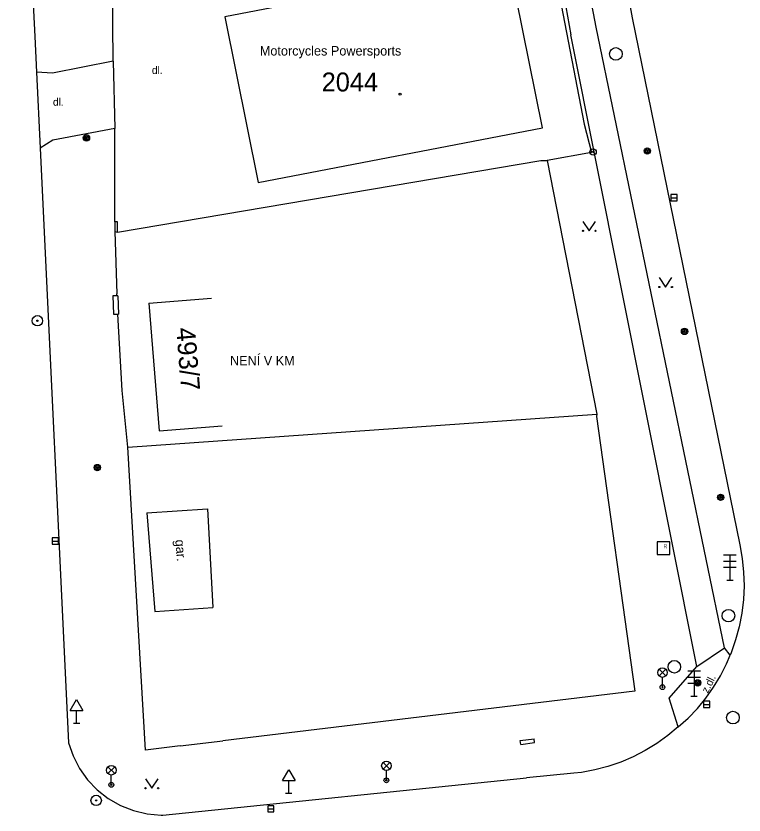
# Model space of a CAD drawing. Extents: x -640201 to -639641, y -1044739 to -1044317.
# Drawn here: x -640163.5 to -640105.9, y -1044617.1 to -1044553.9 of the extents above; entities that cross this region are included whole.
import ezdxf

# ---------------------------------------------------------------- set-up
doc = ezdxf.new("R2010")
doc.units = 0
for name, color, linetype in [('Budovy', 7, 'Continuous'), ('Ploty', 7, 'Continuous'), ('Pol_bod_pole', 7, 'Continuous'), ('Popis objektů', 7, 'Continuous'), ('Popis povrchů', 7, 'Continuous'), ('Popis ČP_ ČE', 7, 'Continuous'), ('Popis-obec_pozn_', 7, 'Continuous'), ('Pris-HUP', 7, 'Continuous'), ('Rozhraní ploch 1', 7, 'Continuous'), ('Rozhraní ploch 2', 7, 'Continuous'), ('Sloupy_označník', 7, 'Continuous'), ('Vstup na pozemky', 7, 'Continuous'), ('Znaky doprava', 7, 'Continuous'), ('Znaky kanalizace', 7, 'Continuous'), ('Značky doprava', 7, 'Continuous'), ('Značky KM', 7, 'Continuous'), ('Značky předmětů', 7, 'Continuous'), ('Šachta sdělovací', 7, 'Continuous')]:
    doc.layers.add(name, color=color, linetype=linetype)

msp = doc.modelspace()

# ---------------------------------------------------------------- linework, layer by layer
at = {"layer": 'Budovy'}
for p, q in [((-640124.51, -1044549.62), (-640147.01, -1044553.94)), ((-640121.86, -1044562.74), (-640124.51, -1044549.62)), ((-640147.01, -1044553.94), (-640144.36, -1044567.06)), ((-640144.36, -1044567.06), (-640121.86, -1044562.74)), ((-640153.03, -1044576.62), (-640148.047, -1044576.21)), ((-640153.03, -1044576.62), (-640152.2, -1044586.72)), ((-640152.2, -1044586.72), (-640147.217, -1044586.31)), ((-640153.18, -1044593.21), (-640148.364, -1044592.877)), ((-640153.18, -1044593.21), (-640152.54, -1044601.02)), ((-640148.364, -1044592.877), (-640147.96, -1044600.689)), ((-640152.54, -1044601.02), (-640147.96, -1044600.689))]:
    msp.add_line(p, q, dxfattribs=at)
at = {"layer": 'Ploty'}
for p, q in [((-640155.72, -1044570.18), (-640155.7, -1044562.79)), ((-640155.49, -1044571), (-640121.97, -1044565.323)), ((-640121.97, -1044565.323), (-640121.472, -1044565.31)), ((-640121.472, -1044565.31), (-640117.548, -1044585.398)), ((-640155.551, -1044576.019), (-640155.56, -1044575.86)), ((-640155.12, -1044583.51), (-640155.467, -1044577.478)), ((-640154.69, -1044588.01), (-640155.12, -1044583.51)), ((-640117.548, -1044585.398), (-640117.57, -1044585.59)), ((-640117.57, -1044585.59), (-640114.54, -1044607.33)), ((-640153.29, -1044611.99), (-640154.69, -1044588.01)), ((-640114.54, -1044607.33), (-640147.15, -1044611.26)), ((-640150.54, -1044611.64), (-640153.29, -1044611.99))]:
    msp.add_line(p, q, dxfattribs=at)
for points in [[(-640121.9, -1044545.04), (-640118.55, -1044562.44)], [(-640155.84, -1044557.46), (-640155.9, -1044551.58)], [(-640118.55, -1044562.44), (-640117.97, -1044564.69), (-640121.472, -1044565.31)]]:
    msp.add_lwpolyline(points, dxfattribs=at)
at = {"layer": 'Pol_bod_pole'}
for centre, radius in [((-640161.84, -1044578), 0.412), ((-640161.84, -1044578), 0.05), ((-640157.19, -1044615.96), 0.412), ((-640157.19, -1044615.96), 0.05)]:
    msp.add_circle(centre, radius, dxfattribs=at)
at = {"layer": 'Pris-HUP'}
for p, q in [((-640155.87, -1044576.03), (-640155.82, -1044577.49)), ((-640155.47, -1044576.016), (-640155.42, -1044577.476)), ((-640123.608, -1044611.232), (-640122.518, -1044611.092)), ((-640123.57, -1044611.53), (-640123.608, -1044611.232)), ((-640123.57, -1044611.53), (-640122.48, -1044611.39)), ((-640122.48, -1044611.39), (-640122.518, -1044611.092))]:
    msp.add_line(p, q, dxfattribs=at)
for points in [[(-640155.7, -1044570.95), (-640155.49, -1044571), (-640155.511, -1044570.175), (-640155.72, -1044570.18), (-640155.7, -1044570.95)], [(-640155.47, -1044576.016), (-640155.551, -1044576.019), (-640155.87, -1044576.03)], [(-640155.82, -1044577.49), (-640155.467, -1044577.478), (-640155.42, -1044577.476)]]:
    msp.add_lwpolyline(points, dxfattribs=at)
at = {"layer": 'Rozhraní ploch 1'}
for p, q in [((-640163.54, -1044524.38), (-640162.05, -1044555.51)), ((-640116.788, -1044543.042), (-640114.749, -1044554.032)), ((-640117.613, -1044554.764), (-640119.575, -1044544.15)), ((-640121.489, -1044544.61), (-640119.614, -1044555.377)), ((-640114.749, -1044554.032), (-640106.227, -1044595.742)), ((-640107.441, -1044603.889), (-640117.613, -1044554.764)), ((-640162.05, -1044555.51), (-640161.916, -1044558.322)), ((-640109.642, -1044605.358), (-640119.614, -1044555.377)), ((-640161.916, -1044558.322), (-640161.628, -1044564.342)), ((-640161.628, -1044564.342), (-640159.38, -1044611.4)), ((-640106.997, -1044604.48), (-640107.441, -1044603.889)), ((-640111.811, -1044607.872), (-640109.642, -1044605.358)), ((-640111.104, -1044610.145), (-640111.811, -1044607.872)), ((-640119.372, -1044613.815), (-640123.115, -1044614.181)), ((-640151.9, -1044617.12), (-640123.115, -1044614.181)), ((-640152.052, -1044617.119), (-640151.9, -1044617.12))]:
    msp.add_line(p, q, dxfattribs=at)
for points in [[(-640155.84, -1044557.46), (-640160.65, -1044558.4), (-640161.916, -1044558.322)], [(-640155.7, -1044562.79), (-640160.61, -1044563.7), (-640161.628, -1044564.342)], [(-640106.227, -1044595.742), (-640106.036, -1044596.813), (-640105.925, -1044597.895), (-640105.893, -1044598.983), (-640105.941, -1044600.07), (-640106.069, -1044601.15), (-640106.276, -1044602.218), (-640106.561, -1044603.268), (-640106.922, -1044604.294), (-640106.997, -1044604.48)], [(-640111.104, -1044610.145), (-640110.315, -1044609.442), (-640109.582, -1044608.68), (-640108.908, -1044607.866), (-640108.298, -1044607.003), (-640107.754, -1044606.096), (-640107.281, -1044605.151), (-640106.997, -1044604.48)], [(-640111.104, -1044610.145), (-640111.925, -1044610.836), (-640112.796, -1044611.465), (-640113.71, -1044612.026), (-640114.659, -1044612.516), (-640115.653, -1044612.938), (-640116.669, -1044613.283), (-640117.709, -1044613.552), (-640118.765, -1044613.742), (-640119.372, -1044613.815)], [(-640159.38, -1044611.4), (-640159.02, -1044612.448), (-640158.513, -1044613.434), (-640157.869, -1044614.336), (-640157.103, -1044615.136), (-640156.229, -1044615.818), (-640155.267, -1044616.367), (-640154.235, -1044616.772), (-640153.156, -1044617.025), (-640152.052, -1044617.119)]]:
    msp.add_lwpolyline(points, dxfattribs=at)
at = {"layer": 'Rozhraní ploch 2'}
for p, q in [((-640154.69, -1044588.01), (-640117.548, -1044585.398)), ((-640109.642, -1044605.358), (-640107.441, -1044603.889))]:
    msp.add_line(p, q, dxfattribs=at)
at = {"layer": 'Sloupy_označník'}
for centre, radius in [((-640157.96, -1044563.53), 0.25), ((-640157.96, -1044563.53), 0.158), ((-640157.96, -1044563.53), 0.05), ((-640117.84, -1044564.64), 0.25), ((-640117.84, -1044564.64), 0.05), ((-640113.552, -1044564.56), 0.25), ((-640113.552, -1044564.56), 0.158), ((-640113.552, -1044564.56), 0.05), ((-640110.604, -1044578.846), 0.25), ((-640110.604, -1044578.846), 0.158), ((-640110.604, -1044578.846), 0.05), ((-640157.1, -1044589.62), 0.25), ((-640157.1, -1044589.62), 0.158), ((-640157.1, -1044589.62), 0.05), ((-640107.744, -1044591.983), 0.25), ((-640107.744, -1044591.983), 0.158), ((-640107.744, -1044591.983), 0.05), ((-640109.559, -1044606.663), 0.25), ((-640109.559, -1044606.663), 0.158), ((-640109.559, -1044606.663), 0.05)]:
    msp.add_circle(centre, radius, dxfattribs=at)
at = {"layer": 'Vstup na pozemky'}
for p, q in [((-640155.84, -1044557.46), (-640155.7, -1044562.79)), ((-640155.7, -1044570.95), (-640155.56, -1044575.86)), ((-640150.54, -1044611.64), (-640147.15, -1044611.26))]:
    msp.add_line(p, q, dxfattribs=at)
at = {"layer": 'Znaky doprava'}
for p, q in [((-640107.506, -1044596.525), (-640106.506, -1044596.525)), ((-640107.506, -1044597.025), (-640106.506, -1044597.025)), ((-640107.006, -1044596.525), (-640107.006, -1044598.525)), ((-640106.506, -1044597.525), (-640107.506, -1044597.525)), ((-640107.256, -1044598.525), (-640106.756, -1044598.525)), ((-640112.617, -1044605.584), (-640112.087, -1044606.114)), ((-640112.617, -1044606.114), (-640112.087, -1044605.584)), ((-640110.351, -1044605.715), (-640109.351, -1044605.715)), ((-640109.851, -1044605.715), (-640109.851, -1044607.715)), ((-640112.352, -1044606.999), (-640112.352, -1044606.224)), ((-640110.351, -1044606.215), (-640109.351, -1044606.215)), ((-640109.351, -1044606.715), (-640110.351, -1044606.715)), ((-640110.101, -1044607.715), (-640109.601, -1044607.715)), ((-640156.255, -1044613.315), (-640155.725, -1044613.845)), ((-640156.255, -1044613.845), (-640155.725, -1044613.315)), ((-640134.475, -1044612.955), (-640133.945, -1044613.485)), ((-640134.475, -1044613.485), (-640133.945, -1044612.955)), ((-640155.99, -1044614.73), (-640155.99, -1044613.955)), ((-640134.21, -1044614.37), (-640134.21, -1044613.595))]:
    msp.add_line(p, q, dxfattribs=at)
for centre, radius in [((-640112.352, -1044605.849), 0.375), ((-640112.352, -1044606.999), 0.19), ((-640112.352, -1044606.999), 0.05), ((-640134.21, -1044613.22), 0.375), ((-640155.99, -1044613.58), 0.375), ((-640155.99, -1044614.73), 0.19), ((-640155.99, -1044614.73), 0.05), ((-640134.21, -1044614.37), 0.19), ((-640134.21, -1044614.37), 0.05)]:
    msp.add_circle(centre, radius, dxfattribs=at)
at = {"layer": 'Znaky kanalizace'}
for p, q in [((-640111.677, -1044568.267), (-640111.177, -1044568.267)), ((-640160.68, -1044595.44), (-640160.18, -1044595.44)), ((-640109.104, -1044608.361), (-640108.604, -1044608.361)), ((-640143.61, -1044616.63), (-640143.11, -1044616.63))]:
    msp.add_line(p, q, dxfattribs=at)
for points in [[(-640111.677, -1044568.517), (-640111.177, -1044568.517), (-640111.177, -1044568.017), (-640111.677, -1044568.017)], [(-640160.68, -1044595.69), (-640160.18, -1044595.69), (-640160.18, -1044595.19), (-640160.68, -1044595.19)], [(-640109.104, -1044608.611), (-640108.604, -1044608.611), (-640108.604, -1044608.111), (-640109.104, -1044608.111)], [(-640143.61, -1044616.88), (-640143.11, -1044616.88), (-640143.11, -1044616.38), (-640143.61, -1044616.38)]]:
    msp.add_lwpolyline(points, close=True, dxfattribs=at)
for centre in [(-640116.041, -1044556.88), (-640107.124, -1044601.343), (-640111.41, -1044605.39), (-640106.768, -1044609.413)]:
    msp.add_circle(centre, 0.5, dxfattribs=at)
at = {"layer": 'Značky doprava'}
for p, q in [((-640159.24, -1044608.84), (-640158.74, -1044607.99)), ((-640158.74, -1044607.99), (-640158.24, -1044608.84)), ((-640159.24, -1044608.84), (-640158.24, -1044608.84)), ((-640158.74, -1044609.84), (-640158.74, -1044608.84)), ((-640158.99, -1044609.84), (-640158.49, -1044609.84)), ((-640142.44, -1044614.39), (-640141.94, -1044613.54)), ((-640141.94, -1044613.54), (-640141.44, -1044614.39)), ((-640142.44, -1044614.39), (-640141.44, -1044614.39)), ((-640141.94, -1044615.39), (-640141.94, -1044614.39)), ((-640142.19, -1044615.39), (-640141.69, -1044615.39))]:
    msp.add_line(p, q, dxfattribs=at)
at = {"layer": 'Značky KM'}
for p, q in [((-640118.65, -1044570.136), (-640118.15, -1044570.886)), ((-640118.15, -1044570.886), (-640117.65, -1044570.136)), ((-640112.6, -1044574.58), (-640112.1, -1044575.33)), ((-640112.1, -1044575.33), (-640111.6, -1044574.58)), ((-640153.284, -1044614.255), (-640152.784, -1044615.005)), ((-640152.784, -1044615.005), (-640152.284, -1044614.255))]:
    msp.add_line(p, q, dxfattribs=at)
for centre in [(-640118.65, -1044570.886), (-640117.65, -1044570.886), (-640112.6, -1044575.33), (-640111.6, -1044575.33), (-640153.284, -1044615.005), (-640152.284, -1044615.005)]:
    msp.add_circle(centre, 0.05, dxfattribs=at)
at = {"layer": 'Značky předmětů'}
msp.add_circle((-640133.124, -1044560.069), 0.0875, dxfattribs=at)
at = {"layer": 'Šachta sdělovací'}
msp.add_lwpolyline([(-640112.773, -1044596.5), (-640111.773, -1044596.5), (-640111.773, -1044595.5), (-640112.773, -1044595.5)], close=True, dxfattribs=at)

# ---------------------------------------------------------------- texts
at = {"layer": 'Popis objektů'}
msp.add_text('Motorcycles Powersports', height=0.75, dxfattribs=at).set_placement((-640144.234, -1044557.011))
msp.add_text('gar.', height=0.75, rotation=274.68471, dxfattribs=at).set_placement((-640150.932, -1044595.35))
at = {"layer": 'Popis povrchů'}
for p in [(-640152.777, -1044558.466), (-640160.61, -1044560.984)]:
    msp.add_text('dl.', height=0.6, dxfattribs=at).set_placement(p)
msp.add_text('z.dl.', height=0.6, rotation=63.4107, dxfattribs=at).set_placement((-640108.759, -1044607.52))
at = {"layer": 'Popis ČP_ ČE'}
msp.add_text('2044', height=1.5, dxfattribs=at).set_placement((-640139.334, -1044559.855))
msp.add_text('493/7', height=1.5, rotation=274.69791, dxfattribs=at).set_placement((-640150.861, -1044578.589))
at = {"layer": 'Popis-obec_pozn_'}
msp.add_text('NENÍ V KM', height=0.75, dxfattribs=at).set_placement((-640146.593, -1044581.535))
at = {"layer": 'Šachta sdělovací'}
msp.add_text('R', height=0.3, dxfattribs=at).set_placement((-640112.273, -1044596))

doc.saveas('drawing.dxf')
